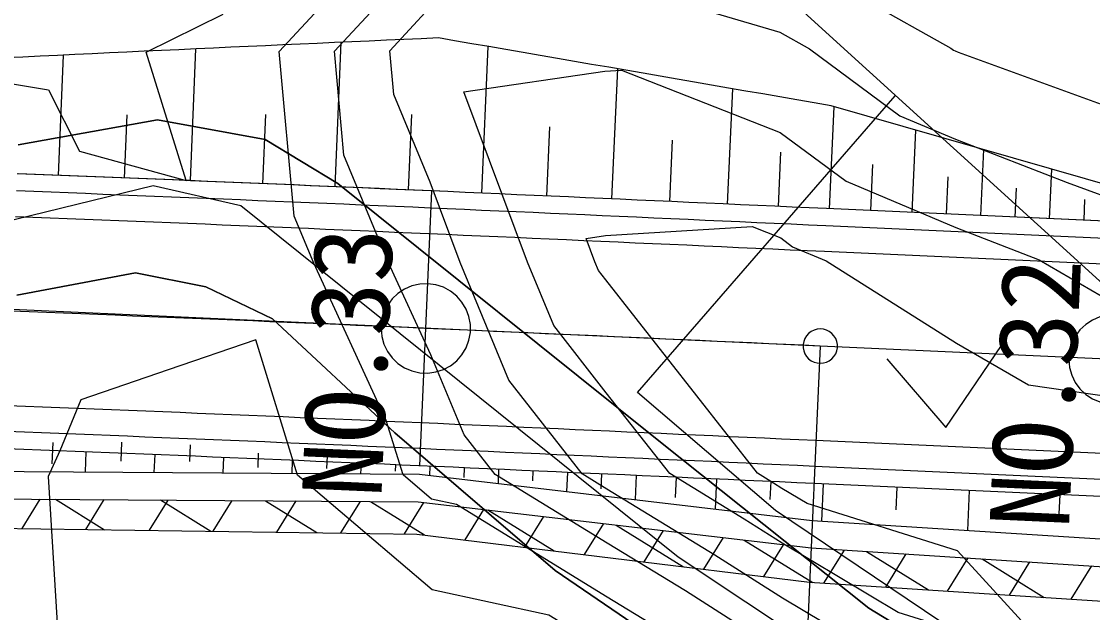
# Model space of a CAD drawing. Extents: x 42655 to 43811, y -141820 to -141156.
# Drawn here: x 43416.61 to 43447.72, y -141348.28 to -141331.1 of the extents above; entities that cross this region are included whole.
import ezdxf

# ---------------------------------------------------------------- set-up
doc = ezdxf.new("R2010")
doc.units = 0
for name, color, linetype in [('D-BMK-HTXT_1', 7, 'Continuous'), ('D-BMK_1', 7, 'Continuous'), ('D-STR', 7, 'Continuous'), ('D-STR-STR4_1', 7, 'Continuous'), ('D-STR_1', 7, 'Continuous'), ('ZE_HICN', 7, 'Continuous'), ('ZE_LWCN', 7, 'Continuous'), ('地形', 7, 'Continuous'), ('現況水路ﾊｯﾁ', 7, 'Continuous')]:
    doc.layers.add(name, color=color, linetype=linetype)

msp = doc.modelspace()

# ---------------------------------------------------------------- linework, layer by layer
at = {"layer": 'D-BMK-HTXT_1'}
for p, q in [((43439.808, -141340.537), (43274.802, -141333.044)), ((43428.176, -141344.019), (43428.525, -141336.027)), ((43439.808, -141340.537), (43436.224, -141419.456))]:
    msp.add_line(p, q, dxfattribs=at)
for points in [[(43427.05, -141340.023), (43427.071, -141340.255), (43427.133, -141340.48), (43427.234, -141340.69), (43427.371, -141340.878), (43427.54, -141341.039), (43427.734, -141341.168), (43427.949, -141341.259), (43428.176, -141341.311), (43428.409, -141341.322), (43428.64, -141341.29), (43428.861, -141341.218), (43429.067, -141341.108), (43429.249, -141340.962), (43429.402, -141340.787), (43429.522, -141340.587), (43429.604, -141340.369), (43429.645, -141340.139), (43429.645, -141339.906), (43429.604, -141339.677), (43429.522, -141339.459), (43429.402, -141339.259), (43429.249, -141339.083), (43429.067, -141338.938), (43428.861, -141338.827), (43428.64, -141338.755), (43428.409, -141338.724), (43428.176, -141338.735), (43427.949, -141338.786), (43427.734, -141338.878), (43427.54, -141339.006), (43427.371, -141339.168), (43427.234, -141339.356), (43427.133, -141339.566), (43427.071, -141339.791), (43427.05, -141340.023)], [(43447.928, -141339.687), (43447.714, -141339.779), (43447.52, -141339.907), (43447.351, -141340.069), (43447.214, -141340.257), (43447.113, -141340.467), (43447.051, -141340.692), (43447.03, -141340.924)], [(43447.03, -141340.924), (43447.051, -141341.156), (43447.113, -141341.381), (43447.214, -141341.591), (43447.351, -141341.779), (43447.52, -141341.94), (43447.714, -141342.069), (43447.928, -141342.16)]]:
    msp.add_lwpolyline(points, dxfattribs=at)
at = {"layer": 'D-BMK_1'}
for points in [[(43648.124, -141349.997), (43439.808, -141340.537), (43439.309, -141340.514), (43438.809, -141340.492), (43438.31, -141340.469), (43437.81, -141340.446), (43437.311, -141340.424), (43436.811, -141340.401), (43436.312, -141340.378), (43435.812, -141340.356), (43435.313, -141340.333), (43434.813, -141340.311), (43434.314, -141340.288), (43433.814, -141340.266), (43433.315, -141340.243), (43432.815, -141340.221), (43432.316, -141340.198), (43431.816, -141340.176), (43431.317, -141340.154), (43430.817, -141340.132), (43430.318, -141340.109), (43429.818, -141340.087), (43429.319, -141340.065), (43428.819, -141340.043), (43428.32, -141340.022), (43427.82, -141340), (43427.321, -141339.978), (43426.821, -141339.956), (43426.322, -141339.935), (43425.822, -141339.913), (43425.322, -141339.892), (43424.823, -141339.87), (43424.323, -141339.849), (43423.824, -141339.828), (43423.324, -141339.807), (43422.825, -141339.786), (43422.325, -141339.765), (43421.826, -141339.745), (43421.326, -141339.724), (43420.826, -141339.703), (43420.327, -141339.683), (43419.827, -141339.663), (43419.328, -141339.643), (43418.828, -141339.623), (43418.328, -141339.603), (43417.829, -141339.583), (43417.329, -141339.564), (43416.83, -141339.544), (43416.33, -141339.525)], [(43439.808, -141340.037), (43439.716, -141340.045), (43439.627, -141340.071), (43439.545, -141340.112), (43439.471, -141340.167), (43439.409, -141340.236), (43439.361, -141340.314), (43439.327, -141340.4), (43439.31, -141340.491), (43439.31, -141340.583), (43439.327, -141340.674), (43439.361, -141340.76), (43439.409, -141340.838), (43439.471, -141340.906), (43439.545, -141340.962), (43439.627, -141341.003), (43439.716, -141341.028), (43439.808, -141341.037)], [(43439.808, -141341.037), (43439.9, -141341.028), (43439.989, -141341.003), (43440.071, -141340.962), (43440.145, -141340.906), (43440.207, -141340.838), (43440.256, -141340.76), (43440.289, -141340.674), (43440.306, -141340.583), (43440.306, -141340.491), (43440.289, -141340.4), (43440.256, -141340.314), (43440.207, -141340.236), (43440.145, -141340.167), (43440.071, -141340.112), (43439.989, -141340.071), (43439.9, -141340.045), (43439.808, -141340.037)]]:
    msp.add_lwpolyline(points, dxfattribs=at)
at = {"layer": 'D-STR'}
for p, q in [((43417.143, -141344.986), (43416.614, -141345.841)), ((43417.593, -141344.989), (43419.022, -141345.874)), ((43419.003, -141344.999), (43418.465, -141345.866)), ((43420.862, -141345.012), (43420.317, -141345.892)), ((43420.642, -141345.01), (43422.106, -141345.917)), ((43422.721, -141345.025), (43422.168, -141345.918)), ((43423.692, -141345.032), (43425.19, -141345.96)), ((43424.58, -141345.038), (43424.019, -141345.944)), ((43426.44, -141345.051), (43425.871, -141345.969)), ((43426.741, -141345.053), (43428.315, -141346.028)), ((43428.288, -141345.081), (43427.722, -141345.995)), ((43430.029, -141345.286), (43429.48, -141346.171)), ((43430.157, -141345.301), (43432.077, -141346.491)), ((43431.769, -141345.491), (43431.215, -141346.385)), ((43433.51, -141345.695), (43432.951, -141346.598)), ((43433.878, -141345.739), (43435.84, -141346.954)), ((43435.25, -141345.9), (43434.686, -141346.812)), ((43436.991, -141346.105), (43436.421, -141347.025)), ((43437.599, -141346.176), (43439.591, -141347.41)), ((43438.731, -141346.31), (43438.156, -141347.239)), ((43440.502, -141346.466), (43439.905, -141347.43)), ((43441.149, -141346.508), (43442.954, -141347.625)), ((43442.298, -141346.581), (43441.701, -141347.545)), ((43444.094, -141346.697), (43443.497, -141347.66)), ((43444.512, -141346.723), (43446.317, -141347.841)), ((43445.89, -141346.812), (43445.293, -141347.775)), ((43447.686, -141346.927), (43447.089, -141347.891))]:
    msp.add_line(p, q, dxfattribs=at)
for points in [[(43398.004, -141344.053), (43428.165, -141344.263), (43439.578, -141345.606), (43448.093, -141346.151)], [(43397.238, -141344.847), (43428.129, -141345.063), (43439.542, -141346.405), (43448.056, -141346.951)], [(43398.048, -141345.583), (43428.089, -141346), (43439.496, -141347.404), (43448.011, -141347.95)]]:
    msp.add_lwpolyline(points, dxfattribs=at)
at = {"layer": 'D-STR-STR4_1'}
for p, q in [((43425.716, -141335.905), (43425.896, -141331.705)), ((43417.686, -141335.574), (43417.823, -141332.08)), ((43421.517, -141335.728), (43421.674, -141331.898)), ((43429.978, -141336.091), (43430.166, -141331.829)), ((43433.759, -141336.259), (43433.929, -141332.478)), ((43437.113, -141336.41), (43437.265, -141333.056)), ((43440.079, -141336.545), (43440.214, -141333.579)), ((43419.601, -141335.651), (43419.675, -141333.819)), ((43423.616, -141335.816), (43423.701, -141333.808)), ((43427.847, -141335.997), (43427.943, -141333.804)), ((43431.869, -141336.174), (43431.958, -141334.164)), ((43442.475, -141336.654), (43442.584, -141334.259)), ((43435.436, -141336.335), (43435.516, -141334.551)), ((43438.596, -141336.478), (43438.668, -141334.895)), ((43444.473, -141336.745), (43444.56, -141334.826)), ((43441.277, -141336.599), (43441.338, -141335.259)), ((43446.471, -141336.835), (43446.536, -141335.393)), ((43443.474, -141336.699), (43443.523, -141335.621)), ((43445.472, -141336.79), (43445.51, -141335.95)), ((43447.47, -141336.881), (43447.497, -141336.279)), ((43417.515, -141343.34), (43417.491, -141343.956)), ((43418.478, -141343.612), (43418.455, -141344.196)), ((43419.513, -141343.331), (43419.491, -141343.881)), ((43421.511, -141343.412), (43421.491, -141343.895)), ((43420.476, -141343.693), (43420.455, -141344.21)), ((43422.475, -141343.775), (43422.456, -141344.224)), ((43423.486, -141343.654), (43423.469, -141344.068)), ((43424.473, -141343.859), (43424.457, -141344.238)), ((43425.484, -141343.739), (43425.469, -141344.094)), ((43426.471, -141343.945), (43426.458, -141344.252)), ((43427.47, -141343.988), (43427.462, -141344.171)), ((43428.469, -141344.032), (43428.458, -141344.298)), ((43429.468, -141344.076), (43429.456, -141344.355)), ((43430.467, -141344.12), (43430.449, -141344.532)), ((43431.46, -141344.164), (43431.447, -141344.45)), ((43432.465, -141344.209), (43432.44, -141344.766)), ((43433.458, -141344.254), (43433.439, -141344.684)), ((43434.463, -141344.299), (43434.432, -141345)), ((43435.625, -141344.351), (43435.598, -141344.938)), ((43436.799, -141344.404), (43436.759, -141345.274)), ((43438.369, -141344.476), (43438.345, -141344.997)), ((43439.891, -141344.545), (43439.843, -141345.623)), ((43442.037, -141344.642), (43442.007, -141345.3)), ((43444.136, -141344.738), (43444.083, -141345.894)), ((43446.766, -141344.857), (43446.741, -141345.411))]:
    msp.add_line(p, q, dxfattribs=at)
for points in [[(43448.555, -141335.972), (43440.125, -141333.553), (43439.629, -141333.467), (43439.132, -141333.381), (43438.635, -141333.294), (43438.138, -141333.208), (43437.642, -141333.122), (43437.145, -141333.036), (43436.648, -141332.949), (43436.151, -141332.863), (43435.654, -141332.777), (43435.157, -141332.691), (43434.66, -141332.605), (43434.163, -141332.519), (43433.665, -141332.433), (43433.168, -141332.347), (43432.671, -141332.261), (43432.173, -141332.175), (43431.676, -141332.089), (43431.178, -141332.003), (43430.68, -141331.917), (43430.183, -141331.832), (43429.685, -141331.746), (43429.187, -141331.66), (43428.72, -141331.58), (43428.217, -141331.602), (43427.715, -141331.625), (43427.212, -141331.647), (43426.709, -141331.669), (43426.206, -141331.692), (43425.703, -141331.714), (43425.2, -141331.737), (43424.697, -141331.759), (43424.194, -141331.782), (43423.691, -141331.805), (43423.188, -141331.828), (43422.685, -141331.851), (43422.182, -141331.874), (43421.679, -141331.897), (43421.176, -141331.921), (43420.672, -141331.944), (43420.169, -141331.968), (43419.666, -141331.992), (43419.162, -141332.016), (43418.659, -141332.04), (43418.156, -141332.064), (43417.652, -141332.088), (43417.149, -141332.113), (43416.645, -141332.137), (43416.142, -141332.162)], [(43448.512, -141336.928), (43439.99, -141336.541), (43439.49, -141336.518), (43438.991, -141336.496), (43438.491, -141336.473), (43437.991, -141336.45), (43437.492, -141336.428), (43436.992, -141336.405), (43436.493, -141336.382), (43435.993, -141336.36), (43435.493, -141336.337), (43434.993, -141336.315), (43434.494, -141336.292), (43433.994, -141336.27), (43433.494, -141336.247), (43432.994, -141336.225), (43432.494, -141336.202), (43431.994, -141336.18), (43431.495, -141336.158), (43430.995, -141336.136), (43430.495, -141336.113), (43429.995, -141336.091), (43429.495, -141336.069), (43428.995, -141336.047), (43428.525, -141336.027), (43428.025, -141336.005), (43427.525, -141335.983), (43427.025, -141335.961), (43426.525, -141335.94), (43426.024, -141335.918), (43425.524, -141335.897), (43425.024, -141335.875), (43424.524, -141335.854), (43424.023, -141335.833), (43423.523, -141335.812), (43423.023, -141335.791), (43422.522, -141335.77), (43422.022, -141335.749), (43421.521, -141335.729), (43421.021, -141335.708), (43420.52, -141335.688), (43420.02, -141335.667), (43419.519, -141335.647), (43419.018, -141335.627), (43418.518, -141335.607), (43418.017, -141335.587), (43417.516, -141335.568), (43417.015, -141335.548), (43416.515, -141335.529)]]:
    msp.add_lwpolyline(points, dxfattribs=at)
at = {"layer": 'D-STR_1'}
for points in [[(43518.44, -141340.104), (43439.99, -141336.541), (43439.49, -141336.518), (43438.991, -141336.496), (43438.491, -141336.473), (43437.991, -141336.45), (43437.492, -141336.428), (43436.992, -141336.405), (43436.493, -141336.382), (43435.993, -141336.36), (43435.493, -141336.337), (43434.993, -141336.315), (43434.494, -141336.292), (43433.994, -141336.27), (43433.494, -141336.247), (43432.994, -141336.225), (43432.494, -141336.202), (43431.994, -141336.18), (43431.495, -141336.158), (43430.995, -141336.136), (43430.495, -141336.113), (43429.995, -141336.091), (43429.495, -141336.069), (43428.995, -141336.047), (43428.495, -141336.025), (43427.994, -141336.003), (43427.494, -141335.982), (43426.994, -141335.96), (43426.494, -141335.938), (43425.994, -141335.917), (43425.493, -141335.895), (43424.993, -141335.874), (43424.493, -141335.853), (43423.992, -141335.832), (43423.492, -141335.811), (43422.992, -141335.79), (43422.491, -141335.769), (43421.991, -141335.748), (43421.49, -141335.727), (43420.99, -141335.707), (43420.489, -141335.686), (43419.989, -141335.666), (43419.488, -141335.646), (43418.987, -141335.626), (43418.487, -141335.606), (43417.986, -141335.586), (43417.485, -141335.567), (43416.985, -141335.547), (43416.484, -141335.528)], [(43648.283, -141346.5), (43439.967, -141337.04), (43439.467, -141337.018), (43438.968, -141336.995), (43438.468, -141336.972), (43437.969, -141336.95), (43437.469, -141336.927), (43436.97, -141336.904), (43436.47, -141336.882), (43435.97, -141336.859), (43435.471, -141336.837), (43434.971, -141336.814), (43434.471, -141336.792), (43433.971, -141336.769), (43433.472, -141336.747), (43432.972, -141336.724), (43432.472, -141336.702), (43431.972, -141336.68), (43431.472, -141336.657), (43430.972, -141336.635), (43430.473, -141336.613), (43429.973, -141336.591), (43429.473, -141336.569), (43428.973, -141336.547), (43428.473, -141336.525), (43427.973, -141336.503), (43427.473, -141336.481), (43426.972, -141336.46), (43426.472, -141336.438), (43425.972, -141336.416), (43425.472, -141336.395), (43424.972, -141336.374), (43424.472, -141336.352), (43423.971, -141336.331), (43423.471, -141336.31), (43422.971, -141336.289), (43422.471, -141336.268), (43421.97, -141336.248), (43421.47, -141336.227), (43420.969, -141336.206), (43420.469, -141336.186), (43419.969, -141336.166), (43419.468, -141336.146), (43418.968, -141336.126), (43418.467, -141336.106), (43417.966, -141336.086), (43417.466, -141336.066), (43416.965, -141336.047), (43416.465, -141336.027)], [(43648.249, -141347.25), (43439.933, -141337.79), (43439.433, -141337.767), (43438.934, -141337.744), (43438.434, -141337.722), (43437.935, -141337.699), (43437.435, -141337.676), (43436.936, -141337.654), (43436.436, -141337.631), (43435.936, -141337.608), (43435.437, -141337.586), (43434.937, -141337.563), (43434.437, -141337.541), (43433.938, -141337.518), (43433.438, -141337.496), (43432.938, -141337.473), (43432.439, -141337.451), (43431.939, -141337.429), (43431.439, -141337.407), (43430.939, -141337.384), (43430.439, -141337.362), (43429.94, -141337.34), (43429.44, -141337.318), (43428.94, -141337.296), (43428.44, -141337.274), (43427.94, -141337.252), (43427.44, -141337.231), (43426.94, -141337.209), (43426.44, -141337.187), (43425.94, -141337.166), (43425.44, -141337.144), (43424.94, -141337.123), (43424.44, -141337.102), (43423.94, -141337.081), (43423.44, -141337.059), (43422.94, -141337.039), (43422.439, -141337.018), (43421.939, -141336.997), (43421.439, -141336.976), (43420.939, -141336.956), (43420.439, -141336.935), (43419.938, -141336.915), (43419.438, -141336.895), (43418.938, -141336.875), (43418.437, -141336.855), (43417.937, -141336.835), (43417.437, -141336.816), (43416.936, -141336.796), (43416.436, -141336.777)], [(43647.999, -141352.744), (43439.683, -141343.284), (43439.184, -141343.261), (43438.684, -141343.239), (43438.185, -141343.216), (43437.686, -141343.193), (43437.186, -141343.171), (43436.687, -141343.148), (43436.187, -141343.125), (43435.688, -141343.103), (43435.189, -141343.08), (43434.689, -141343.058), (43434.19, -141343.035), (43433.691, -141343.013), (43433.191, -141342.99), (43432.692, -141342.968), (43432.193, -141342.946), (43431.694, -141342.923), (43431.194, -141342.901), (43430.695, -141342.879), (43430.196, -141342.857), (43429.697, -141342.835), (43429.198, -141342.813), (43428.699, -141342.791), (43428.199, -141342.769), (43427.7, -141342.747), (43427.201, -141342.725), (43426.702, -141342.704), (43426.203, -141342.682), (43425.704, -141342.661), (43425.205, -141342.639), (43424.706, -141342.618), (43424.207, -141342.597), (43423.708, -141342.576), (43423.209, -141342.555), (43422.71, -141342.534), (43422.211, -141342.513), (43421.712, -141342.492), (43421.213, -141342.472), (43420.714, -141342.451), (43420.215, -141342.431), (43419.716, -141342.411), (43419.217, -141342.391), (43418.718, -141342.371), (43418.22, -141342.351), (43417.721, -141342.331), (43417.222, -141342.311), (43416.723, -141342.292), (43416.224, -141342.273)], [(43647.965, -141353.493), (43439.649, -141344.033), (43439.15, -141344.011), (43438.65, -141343.988), (43438.151, -141343.965), (43437.652, -141343.943), (43437.152, -141343.92), (43436.653, -141343.897), (43436.153, -141343.875), (43435.654, -141343.852), (43435.155, -141343.83), (43434.656, -141343.807), (43434.156, -141343.785), (43433.657, -141343.762), (43433.158, -141343.74), (43432.659, -141343.717), (43432.159, -141343.695), (43431.66, -141343.673), (43431.161, -141343.65), (43430.662, -141343.628), (43430.163, -141343.606), (43429.664, -141343.584), (43429.165, -141343.562), (43428.666, -141343.54), (43428.167, -141343.518), (43427.668, -141343.496), (43427.169, -141343.475), (43426.67, -141343.453), (43426.171, -141343.431), (43425.672, -141343.41), (43425.173, -141343.389), (43424.674, -141343.367), (43424.175, -141343.346), (43423.676, -141343.325), (43423.177, -141343.304), (43422.679, -141343.283), (43422.18, -141343.262), (43421.681, -141343.242), (43421.182, -141343.221), (43420.683, -141343.201), (43420.185, -141343.18), (43419.686, -141343.16), (43419.187, -141343.14), (43418.689, -141343.12), (43418.19, -141343.1), (43417.691, -141343.08), (43417.193, -141343.061), (43416.694, -141343.041), (43416.195, -141343.022)], [(43647.943, -141353.993), (43439.627, -141344.533), (43439.127, -141344.51), (43438.628, -141344.487), (43438.128, -141344.465), (43437.629, -141344.442), (43437.13, -141344.419), (43436.63, -141344.397), (43436.131, -141344.374), (43435.632, -141344.352), (43435.132, -141344.329), (43434.633, -141344.307), (43434.134, -141344.284), (43433.635, -141344.262), (43433.135, -141344.239), (43432.636, -141344.217), (43432.137, -141344.194), (43431.638, -141344.172), (43431.139, -141344.15), (43430.64, -141344.128), (43430.141, -141344.106), (43429.642, -141344.083), (43429.143, -141344.061), (43428.644, -141344.04), (43428.145, -141344.018), (43427.646, -141343.996), (43427.147, -141343.974), (43426.648, -141343.953), (43426.149, -141343.931), (43425.65, -141343.909), (43425.152, -141343.888), (43424.653, -141343.867), (43424.154, -141343.846), (43423.655, -141343.825), (43423.156, -141343.804), (43422.658, -141343.783), (43422.159, -141343.762), (43421.66, -141343.741), (43421.162, -141343.721), (43420.663, -141343.7), (43420.164, -141343.68), (43419.666, -141343.66), (43419.167, -141343.64), (43418.669, -141343.62), (43418.17, -141343.6), (43417.672, -141343.58), (43417.173, -141343.561), (43416.675, -141343.541), (43416.176, -141343.522)]]:
    msp.add_lwpolyline(points, dxfattribs=at)
at = {"layer": 'ZE_HICN'}
for points in [[(43434.881, -141330.296), (43438.633, -141331.413), (43439.497, -141331.899), (43442.12, -141333.839), (43443.735, -141334.524), (43446.976, -141335.782), (43448.833, -141336.457), (43453.377, -141337.332), (43453.925, -141337.402), (43454.509, -141337.283), (43457.744, -141337.975), (43459.017, -141338.191), (43463.729, -141338.404), (43464.107, -141338.459), (43464.316, -141338.452), (43464.455, -141338.365), (43465.179, -141337.94), (43467.545, -141335.945), (43469.18, -141335.307), (43472.777, -141331.741), (43473.36, -141330.665)], [(43448.917, -141354.339), (43444.761, -141351.507), (43443.815, -141351.285), (43443.269, -141351.028), (43442.909, -141350.371), (43438.71, -141347.868), (43436.745, -141346.611), (43433.607, -141344.692), (43432.896, -141344.255), (43430.767, -141341.525), (43429.349, -141338.109), (43428.477, -141335.776), (43427.418, -141333.224), (43427.303, -141331.956), (43428.453, -141330.715)]]:
    msp.add_lwpolyline(points, dxfattribs=at)
at = {"layer": 'ZE_LWCN'}
for points in [[(43448.025, -141357.608), (43443.84, -141356.682), (43443.5, -141356.531), (43440.088, -141354.919), (43438.732, -141352.445), (43437.685, -141350.395), (43435.036, -141348.701), (43433.622, -141347.836), (43429.241, -141345.144), (43428.521, -141344.987), (43427.69, -141344.28), (43427.201, -141342.698), (43425.096, -141338.13), (43424.527, -141336.759), (43424.093, -141331.972), (43428.437, -141327.282)], [(43448.924, -141355.793), (43447.557, -141354.861), (43443.828, -141353.988), (43441.679, -141352.973), (43440.259, -141350.383), (43438.718, -141349.464), (43435.89, -141347.656), (43433.615, -141346.264), (43430.365, -141344.267), (43429.466, -141343.115), (43428.501, -141340.789), (43427.27, -141338.119), (43425.973, -141334.991), (43425.698, -141331.964), (43428.445, -141328.998)], [(43438.622, -141329.078), (43443.6, -141331.879), (43443.676, -141331.936), (43443.723, -141331.956), (43443.818, -141331.992), (43448.82, -141333.812), (43450.753, -141334.184), (43453.912, -141334.588), (43457.273, -141333.903), (43458.999, -141334.272), (43461.145, -141334.396), (43464.08, -141332.859), (43464.604, -141332.418), (43466.256, -141331.772), (43469.153, -141329.675)], [(43413.197, -141332.386), (43417.396, -141333.083), (43418.296, -141334.869), (43421.39, -141335.726), (43420.227, -141331.99), (43422.463, -141330.886)], [(43448.91, -141352.886), (43445.204, -141350.36), (43443.803, -141348.826), (43442.069, -141348.278), (43438.703, -141346.271), (43437.599, -141345.566), (43435.437, -141344.243), (43433.594, -141341.892), (43432.067, -141339.934), (43431.306, -141338.1), (43429.454, -141333.145), (43433.55, -141332.548), (43434.04, -141332.518), (43438.646, -141334.325), (43440.563, -141335.743), (43443.748, -141337.091), (43446.166, -141338.03), (43447.972, -141339.079)], [(43448.904, -141351.432), (43447.315, -141350.35), (43443.792, -141346.491), (43439.432, -141345.114), (43438.695, -141344.675), (43438.454, -141344.521), (43437.981, -141344.231), (43433.579, -141338.614), (43433.368, -141338.344), (43433.263, -141338.091), (43433.007, -141337.407), (43433.572, -141337.325), (43437.83, -141337.065), (43438.661, -141337.391), (43439.007, -141337.647), (43439.981, -141338.059), (43443.763, -141340.453), (43445.856, -141341.667), (43448.859, -141342.097)], [(43454.056, -141365.114), (43452.84, -141364.117), (43448.961, -141363.631), (43447.622, -141362.674), (43446.257, -141359.771), (43443.852, -141359.239), (43439.294, -141357.203), (43438.753, -141356.959), (43437.983, -141356.557), (43437.728, -141355.325), (43435.215, -141350.407), (43434.181, -141349.746), (43433.63, -141349.408), (43431.92, -141348.358), (43428.533, -141347.621), (43424.624, -141344.294), (43423.41, -141340.36), (43420.871, -141341.231), (43418.331, -141342.102), (43417.723, -141343.582), (43417.384, -141344.329), (43417.713, -141349.698), (43413.28, -141350.088)]]:
    msp.add_lwpolyline(points, dxfattribs=at)
at = {"layer": '地形'}
for points in [[(43472.544, -141316.076), (43472.249, -141324.334), (43471.363, -141329.348), (43468.116, -141334.755), (43465.362, -141340.064), (43464.771, -141342.718), (43461.623, -141343.308), (43450.996, -141341.44), (43438.795, -141330.331), (43439.877, -141328.464), (43445.683, -141321.779), (43448.733, -141319.321), (43451.291, -141315.487), (43472.544, -141316.076)], [(43464.771, -141342.718), (43464.081, -141346.182), (43463.888, -141350.135), (43464.274, -141351.244), (43454.189, -141352.112), (43446.661, -141350.811), (43438.505, -141345.314), (43434.5, -141341.891), (43441.98, -141333.261)], [(43553.691, -141354.812), (43550.208, -141356.373), (43546.065, -141357.213), (43542.041, -141357.333), (43538.86, -141357.323), (43534.355, -141356.365), (43529.057, -141354.989), (43522.883, -141353.53), (43517.334, -141352.446), (43510.743, -141351.321), (43504.861, -141350.612), (43498.353, -141350.279), (43495.141, -141350.071), (43486.185, -141350.513), (43469.214, -141351.337), (43459.314, -141352.162), (43451.654, -141352.339), (43446.055, -141351.102), (43441.223, -141348.158), (43435.118, -141343.288), (43425.795, -141335.807), (43423.686, -141334.529), (43420.559, -141333.955), (43416.507, -141334.688)], [(43647.722, -141358.843), (43628.878, -141354.259), (43624.278, -141352.34), (43610.656, -141352.746), (43600.049, -141357.9), (43584.108, -141344.001), (43579.575, -141340.103), (43575.981, -141339.003), (43571.17, -141339.119), (43567.866, -141341.494), (43559.565, -141353.262), (43554.745, -141358.368), (43544.775, -141360.801), (43537.008, -141359.816), (43506.675, -141352.748), (43493.73, -141352.632), (43456.856, -141354.434), (43449.599, -141354.085), (43443.512, -141351.884), (43435.686, -141346.669), (43422.979, -141336.46), (43420.429, -141335.881), (43409.299, -141338.603)], [(43416.471, -141339.059), (43419.923, -141338.403), (43421.96, -141338.817), (43423.894, -141339.748), (43427.45, -141343.06), (43432.11, -141347.062), (43435.183, -141349.166), (43438.264, -141351.359), (43441.238, -141353.396), (43443.588, -141354.331), (43445.483, -141355.194), (43448.409, -141355.793), (43451.023, -141356.296), (43453.637, -141356.272), (43459.396, -141356.357), (43466.324, -141356.094), (43473.328, -141355.68), (43481.912, -141355.153)], [(43441.744, -141340.905), (43443.452, -141342.908), (43445.072, -141340.519)]]:
    msp.add_lwpolyline(points, dxfattribs=at)
at = {"layer": '現況水路ﾊｯﾁ'}
for points in [[(43416.507, -141334.688), (43420.559, -141333.955), (43423.686, -141334.529), (43425.795, -141335.807), (43435.118, -141343.288), (43441.223, -141348.158), (43446.055, -141351.102), (43451.654, -141352.339), (43459.314, -141352.162), (43469.214, -141351.337), (43486.185, -141350.513), (43495.141, -141350.071), (43498.353, -141350.279), (43504.861, -141350.612), (43510.743, -141351.321), (43517.334, -141352.446), (43522.883, -141353.53), (43529.057, -141354.989), (43534.355, -141356.365), (43538.86, -141357.323), (43542.041, -141357.333), (43546.065, -141357.213), (43550.208, -141356.373), (43553.691, -141354.812)], [(43481.912, -141355.153), (43473.328, -141355.68), (43466.324, -141356.094), (43459.396, -141356.357), (43453.637, -141356.272), (43451.023, -141356.296), (43448.409, -141355.793), (43445.483, -141355.194), (43443.588, -141354.331), (43441.238, -141353.396), (43438.264, -141351.359), (43435.183, -141349.166), (43432.11, -141347.062), (43427.45, -141343.06), (43423.894, -141339.748), (43421.96, -141338.817), (43419.923, -141338.403), (43416.471, -141339.059)]]:
    msp.add_lwpolyline(points, dxfattribs=at)

# ---------------------------------------------------------------- texts
at = {"layer": 'D-BMK-HTXT_1'}
for s, rotation, p in [('NO.33', 87.4933, (43427.058, -141344.971)), ('NO.32', 87.3991, (43447.029, -141345.87))]:
    msp.add_text(s, height=2.3065, rotation=rotation, dxfattribs=at).set_placement(p)

doc.saveas('drawing.dxf')
